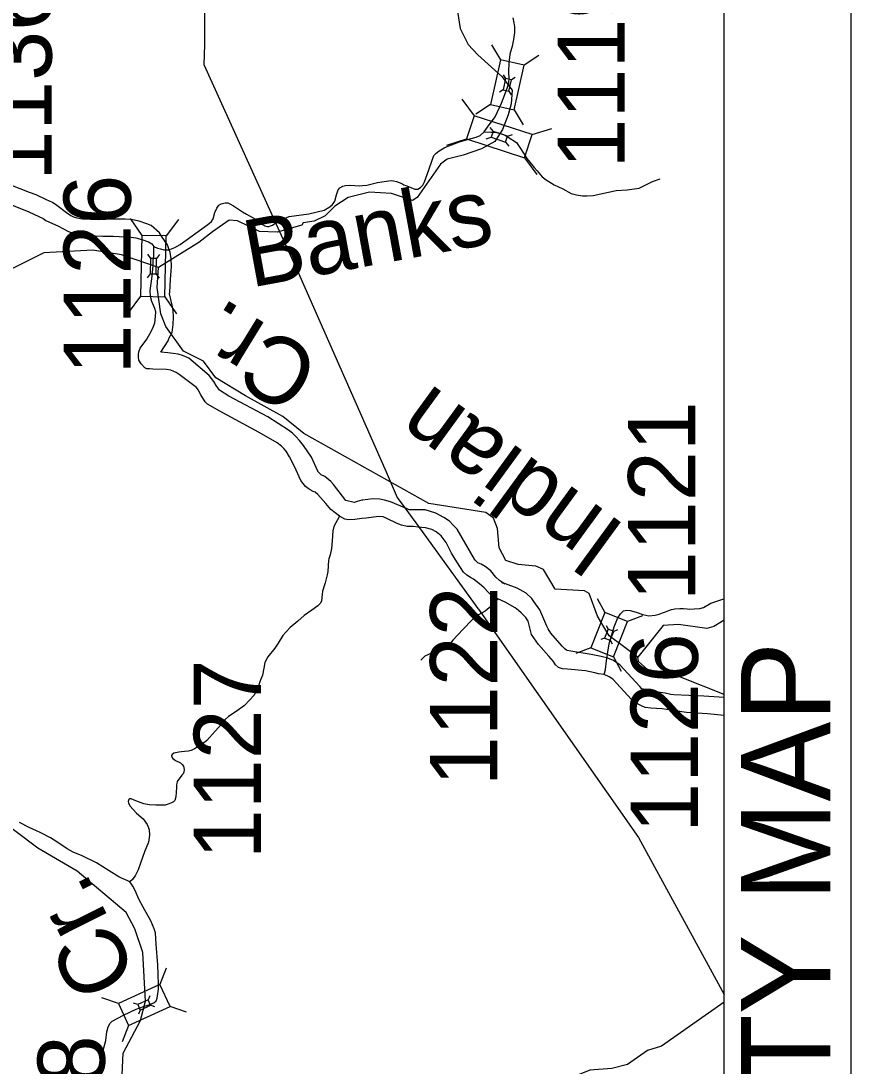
# Model space of a CAD drawing. Extents: x 264770 to 739672, y 157173 to 249791.
# Drawn here: x 727710 to 728336, y 158631 to 159419 of the extents above; entities that cross this region are included whole.
import ezdxf

# ---------------------------------------------------------------- set-up
doc = ezdxf.new("R2010")
doc.units = 0
for name, color, linetype in [('Old_Level_27', 7, 'Continuous'), ('Old_Level_5', 7, 'Continuous'), ('Prop Cable Guiderail Anchor Unit CELL', 7, 'Continuous'), ('Prop Cable Guiderail Single Face', 7, 'Continuous'), ('Prop Conc 2ft 6in Curb and Gutter', 7, 'Continuous'), ('Prop GRAU 350 Approach CELL', 7, 'Continuous'), ('Prop Guardrail Anchor Unit CELL', 7, 'Continuous'), ('Prop Lane Arrow Shared Lt and Thru CELL', 7, 'Continuous'), ('Prop ROW Station Offsets', 7, 'Continuous')]:
    doc.layers.add(name, color=color, linetype=linetype)

msp = doc.modelspace()

# ---------------------------------------------------------------- linework, layer by layer
at = {"layer": 'Old_Level_5'}
for points in [[(728193.27, 159467.91), (728173.62, 159472.65), (728164.12, 159479.96), (728126.72, 159480.62), (728119.2, 159483.78), (728071.56, 159489.46), (728066.92, 159486.7), (728052.97, 159455.09), (728043.68, 159437.89), (728039.77, 159426.35), (728041.58, 159413.46), (728047.77, 159401.58), (728054.96, 159393.65)], [(728054.96, 159393.65), (728073.01, 159377.28), (728080.84, 159367.08), (728080.21, 159356.86), (728077.92, 159348.46), (728073.58, 159337.51), (728067.85, 159328.35), (728057.78, 159322.88), (728044.05, 159318.19), (728031.82, 159315.1), (728026.92, 159311.2), (728009.2, 159286.14), (728005.71, 159283.93), (727989.98, 159289.13), (727973.24, 159290.3), (727957.32, 159286.18), (727947.08, 159279.54), (727939.82, 159272.21), (727931.48, 159268.42), (727923.41, 159266.94), (727922.23, 159265.23), (727903.76, 159260.04), (727890.46, 159260.5), (727873.86, 159268.66), (727867.57, 159269.11), (727854.98, 159260.35), (727844.61, 159252.16), (727839.26, 159248.86), (727814.14, 159233.36)], [(727814.14, 159233.36), (727786.19, 159242.83), (727764.61, 159246.42), (727727.83, 159244.55), (727698.6, 159229.8), (727682.21, 159225.12), (727664.77, 159225.14), (727659.53, 159227.66), (727647.4, 159229.24), (727639.07, 159226.03), (727629.13, 159211.21), (727614.24, 159201.22), (727611.1, 159193.75), (727620.47, 159180.01), (727617.34, 159172.53), (727597.65, 159174.96), (727591.65, 159173.41)], [(728175.64, 158939.69), (728154.15, 158955.6), (728145.26, 158970.5), (728138.95, 158987.63), (728135.54, 158989.51), (728113.3, 158990.85), (728104.41, 159005.75), (728098.72, 159008.28), (728085.42, 159009.32), (728076.07, 159012.56), (728071.22, 159022.07), (728069.9, 159036.68), (728066.84, 159044.38), (728060.95, 159048.67), (728018.16, 159055.41), (727923.7, 159108.25), (727907.88, 159121.05), (727879.73, 159136.6), (727857.5, 159150.22), (727848.11, 159162.79), (727833.11, 159170.31), (727819.7, 159188.86), (727815.98, 159198.32), (727813.17, 159218.25), (727814.14, 159233.36)], [(728240.88, 158967.57), (728233.04, 158962.78), (728227.73, 158961.22), (728206.43, 158964.29), (728194.71, 158963.53), (728175.64, 158939.69)], [(728240.88, 158911.43), (728207.94, 158924.56), (728185.29, 158928.28), (728176.26, 158936.18), (728175.64, 158939.69)], [(727786.89, 158624.71), (727787.45, 158641.02), (727800.56, 158665.66), (727804.53, 158680.1), (727802.28, 158716.94), (727796.43, 158734.63), (727789.79, 158747.12), (727752.99, 158778.14), (727723.25, 158795.51), (727675.98, 158830.99), (727666.23, 158848.82), (727659.48, 158855.48), (727637.57, 158862.06), (727581.54, 158861.66)], [(728240.88, 158679.51), (728193.45, 158646.22), (728183.06, 158643.08), (728167.92, 158632.53), (728156.15, 158629.43), (728139.37, 158628.26), (728131.5, 158625.02), (728124.9, 158616.5), (728114.35, 158582.47), (728098.42, 158543.34), (728095.35, 158538.78)]]:
    msp.add_lwpolyline(points, dxfattribs=at)
at = {"layer": 'Prop Conc 2ft 6in Curb and Gutter'}
for p, q in [((728065.25, 159401.22), (728072.03, 159389.93)), ((728100.91, 159393.21), (728089.95, 159385.91)), ((728074.22, 159378.65), (728075.92, 159375.83)), ((728083.14, 159376.65), (728080.4, 159374.82)), ((728074.03, 159367.43), (728071.29, 159365.61)), ((728078.51, 159366.42), (728080.21, 159363.6)), ((728042.95, 159360.36), (728052.22, 159347.78)), ((728064.49, 159356.35), (728053.52, 159349.04)), ((728082.4, 159352.32), (728089.18, 159341.03)), ((728064.14, 159339.05), (728066.46, 159335.91)), ((728061.31, 159330.37), (728065.04, 159331.55)), ((728077.37, 159332.36), (728081.09, 159333.54)), ((728095.87, 159333.58), (728110.76, 159338.3)), ((728031.65, 159325.61), (728046.54, 159330.32)), ((728075.95, 159328), (728078.27, 159324.85)), ((728090.19, 159316.12), (728099.46, 159303.54)), ((727792.77, 159270.43), (727801.6, 159257.54)), ((727829.31, 159269.67), (727819.96, 159257.16)), ((727805.92, 159243.41), (727808.13, 159240.19)), ((727815.05, 159243.22), (727812.71, 159240.09)), ((727807.89, 159228.72), (727805.55, 159225.59)), ((727812.47, 159228.62), (727814.68, 159225.4)), ((727800.64, 159211.65), (727791.29, 159199.14)), ((727819, 159211.27), (727827.83, 159198.38)), ((728145.1, 158983.92), (728150.69, 158973.22)), ((728179.15, 158970.66), (728167.8, 158966.56)), ((728151.81, 158963.38), (728153.2, 158960.7)), ((728150.6, 158954.02), (728147.76, 158952.99)), ((728160.32, 158960.06), (728157.48, 158959.04)), ((728140.28, 158946.49), (728128.93, 158942.39)), ((728154.88, 158952.35), (728156.28, 158949.68)), ((728157.39, 158939.83), (728162.99, 158929.13)), ((727820.08, 158705.13), (727815.22, 158692.89)), ((727783.94, 158678.51), (727771.48, 158682.8)), ((727798.54, 158677.65), (727795.43, 158678.72)), ((727807.58, 158684.3), (727806.36, 158681.24)), ((727811.39, 158676), (727808.28, 158677.07)), ((727800.46, 158673.47), (727799.24, 158670.41)), ((727835.34, 158671.92), (727822.88, 158676.2)), ((727791.6, 158661.83), (727786.74, 158649.59))]:
    msp.add_line(p, q, dxfattribs=at)
for points in [[(728082.4, 159352.32), (728089.95, 159385.91), (728072.03, 159389.93), (728064.49, 159356.35)], [(728095.87, 159333.58), (728052.22, 159347.78), (728046.54, 159330.32), (728090.19, 159316.12)], [(727819, 159211.27), (727819.96, 159257.16), (727801.6, 159257.54), (727800.64, 159211.65)], [(728157.39, 158939.83), (728167.8, 158966.56), (728150.69, 158973.22), (728140.28, 158946.49)], [(727791.6, 158661.83), (727822.88, 158676.2), (727815.22, 158692.89), (727783.94, 158678.51)]]:
    msp.add_lwpolyline(points, close=True, dxfattribs=at)
for points in [[(728078.51, 159366.42), (728080.4, 159374.82), (728075.92, 159375.83), (728074.03, 159367.43), (728078.51, 159366.42)], [(728077.37, 159332.36), (728066.46, 159335.91), (728065.04, 159331.55), (728075.95, 159328), (728077.37, 159332.36)], [(727812.47, 159228.62), (727812.71, 159240.09), (727808.13, 159240.19), (727807.89, 159228.72), (727812.47, 159228.62)], [(728154.88, 158952.35), (728157.48, 158959.04), (728153.2, 158960.7), (728150.6, 158954.02), (728154.88, 158952.35)], [(727800.46, 158673.47), (727808.28, 158677.07), (727806.36, 158681.24), (727798.54, 158677.65), (727800.46, 158673.47)]]:
    msp.add_lwpolyline(points, dxfattribs=at)
at = {"layer": 'Prop GRAU 350 Approach CELL'}
for p, q in [((728240.88, 157172.59), (728240.88, 160226.7)), ((728336.48, 157210.09), (728336.48, 160189.2))]:
    msp.add_line(p, q, dxfattribs=at)
at = {"layer": 'Prop Guardrail Anchor Unit CELL'}
for p, q in [((727848.8, 159459.04), (727848.9, 159401.21)), ((727848.9, 159401.21), (727848.43, 159386.41)), ((727848.43, 159386.41), (727903.06, 159266.08)), ((727903.06, 159266.08), (727919.86, 159229.08)), ((727919.86, 159229.08), (727985.81, 159079.32)), ((727985.81, 159079.32), (727994.28, 159060.07)), ((727994.28, 159060.07), (728000.07, 159052.09)), ((728000.07, 159052.09), (728011.03, 159036.98)), ((728055.39, 158975.81), (728176.24, 158803.57)), ((728176.24, 158803.57), (728240.88, 158685.14))]:
    msp.add_line(p, q, dxfattribs=at)
msp.add_lwpolyline([(728011.03, 159036.98), (728055.06, 158976.28), (728055.39, 158975.81)], dxfattribs=at)
at = {"layer": 'Prop Lane Arrow Shared Lt and Thru CELL'}
for points in [[(728078.44, 159372.68), (728078.6, 159376.17), (728078.47, 159380.39), (728078.67, 159388.28), (728079.59, 159395.38), (728081.14, 159400.22), (728082.16, 159405.24), (728082.82, 159410.63), (728082.95, 159412.84), (728082.82, 159414.74), (728082.35, 159417.9), (728081.7, 159421.58)], [(728059.7, 159335.79), (728062.4, 159339.27), (728068.05, 159347.04), (728072.85, 159357.29), (728075.48, 159363.74), (728077.32, 159369.46), (728078.44, 159372.68)], [(727810.71, 159249.28), (727813.41, 159248.03), (727815.81, 159247.34), (727818.28, 159246.58), (727820.57, 159246.58), (727822.26, 159246.79), (727822.78, 159246.85), (727826.58, 159248.41), (727830.66, 159250.62), (727851.31, 159265.74), (727854.27, 159268.17), (727855.39, 159270.14), (727856.77, 159274.81), (727858.15, 159278.16), (727859.73, 159280.33), (727861.37, 159281.39), (727864.52, 159282.25), (727866.49, 159282.05), (727868.01, 159281.46), (727870.83, 159279.94), (727877.55, 159275.34), (727880.64, 159273.5), (727882.81, 159272.38), (727885.18, 159271.07), (727887.34, 159269.72), (727889.43, 159268.67), (727890.96, 159267.35), (727892.68, 159265.73), (727894.31, 159264.9), (727896.32, 159264.26), (727897.47, 159264.3), (727898.59, 159264.69), (727900.23, 159265.41), (727903.32, 159267.45), (727904.84, 159268.37), (727907.34, 159269.69), (727912.81, 159271.73), (727927.68, 159273.83), (727939.13, 159276.51), (727943.34, 159279.07), (727945.38, 159280.91), (727947.09, 159283.48), (727948.47, 159288.08), (727949.79, 159291.96), (727950.89, 159293.41), (727953.26, 159294.59), (727955.3, 159295.12), (727958.53, 159295.45), (727962.21, 159295.18), (727965.7, 159295.05), (727968.07, 159295.12), (727971.29, 159295.38), (727979.47, 159297.42), (727984.41, 159298.34), (727987.83, 159298.73), (727989.87, 159298.86), (727991.45, 159298.67), (727993.62, 159298.21), (727997.61, 159296.59), (727999.25, 159295.69), (728001.53, 159294.91), (728007.56, 159292.49), (728009.66, 159292.55), (728011.7, 159293.67), (728013.48, 159295.51), (728014.86, 159297.88), (728016.9, 159303.6), (728019.97, 159312.81), (728021.91, 159317.78), (728023.52, 159319.64), (728025.82, 159321.35), (728029.5, 159323.65), (728033.24, 159325.2), (728041.27, 159328.09), (728048.97, 159330.39), (728053.85, 159331.71), (728056.68, 159333.02), (728059.7, 159335.79)], [(728059.7, 159335.79), (728064.9, 159335.52), (728068.72, 159335.46), (728071.28, 159334.6), (728074.27, 159333.62)], [(728074.27, 159333.62), (728077.76, 159331.58), (728084.21, 159327.5), (728086.64, 159323.95), (728089.86, 159318.76), (728091.9, 159315.53), (728097.43, 159308.69), (728099.86, 159306.2), (728103.62, 159301.65), (728106.51, 159299.42), (728112.63, 159295.8), (728119.14, 159292.71), (728125.39, 159289.09), (728129.41, 159288.24), (728133.81, 159287.38), (728137.3, 159287.32), (728142.1, 159287.71), (728159.34, 159291.53), (728167.57, 159291.92), (728176.57, 159293.3), (728186.63, 159298.23), (728192.42, 159300.27)], [(727692.76, 159284.57), (727712.08, 159277.06), (727716.55, 159275.46), (727723.92, 159271.89), (727727.29, 159270.36), (727729.37, 159268.89), (727738.81, 159264.5), (727745.79, 159260.69), (727750.13, 159259.11), (727753.55, 159258.32), (727758.55, 159257.79), (727766.71, 159257.27), (727772.16, 159256.97), (727780.18, 159256.91), (727784.58, 159256.71), (727791.95, 159256.38), (727797.18, 159255.66), (727801.66, 159254.54), (727806.72, 159252.7), (727809.16, 159251.25), (727810.71, 159249.28)], [(727810.26, 159234.68), (727810.25, 159238.95), (727810.58, 159241.72), (727810.65, 159243.82), (727810.65, 159246.19), (727810.71, 159249.28)], [(727950.66, 159045.77), (727944.14, 159051.03), (727940.41, 159055.44), (727934.36, 159062.32), (727932.33, 159063.86), (727930.92, 159064.55), (727928.55, 159065.74), (727927.05, 159066.75), (727925.09, 159068.27), (727921.6, 159072.88), (727916.86, 159083.21), (727912.98, 159090.64), (727910.49, 159094.84), (727908.78, 159097.01), (727906.94, 159098.72), (727903.65, 159101.23), (727890.18, 159108.99), (727860, 159125.24), (727853.31, 159128.98), (727851.14, 159130.44), (727849.43, 159132.2), (727846.12, 159137.47), (727844.15, 159141.15), (727842.77, 159142.91), (727829.87, 159152.77), (727827.64, 159154.1), (727825.86, 159155.01), (727823.42, 159156.06), (727820.26, 159156.52), (727809.93, 159156.65), (727807.43, 159156.85), (727805.46, 159157.05), (727804.01, 159157.64), (727801.12, 159160.67), (727799.47, 159163.5), (727799.14, 159166.06), (727799.17, 159167.8), (727799.28, 159169.75), (727800.46, 159172.51), (727805.53, 159179.41), (727808.95, 159185.59), (727810.13, 159188.49), (727811.49, 159191.66), (727811.91, 159196.34), (727812.11, 159199.83), (727811.45, 159202.53), (727809.28, 159207.65), (727808.16, 159211.47), (727807.83, 159216.07), (727809.15, 159224.82), (727810.26, 159234.68)], [(727950.66, 159045.77), (727946.31, 159038.08), (727945.66, 159034.86), (727945.26, 159027.18), (727944.6, 159021.39), (727943.68, 159016.72), (727942.56, 159013.83), (727942.38, 159012.8), (727942.1, 159008.38), (727941.93, 159004.18), (727941.44, 159001.76), (727939.8, 158995.58), (727937.96, 158989.27), (727937.63, 158986.77), (727937.23, 158982.17), (727936.38, 158980.19), (727934.34, 158978.16), (727929.8, 158975), (727924.09, 158970.9), (727919.39, 158966.73), (727913.53, 158961.93), (727910.24, 158958.44), (727907.94, 158955.83), (727904.46, 158950.18), (727901.95, 158946.36), (727896.76, 158939.72), (727894.28, 158935.5), (727893.69, 158931.29), (727892.62, 158926.05), (727890.86, 158921.69), (727890.07, 158919.46), (727889.55, 158918.07), (727887.31, 158912.81), (727886.19, 158910.64), (727882.9, 158907.09), (727879.05, 158903.14), (727872.79, 158898.64), (727866.93, 158894.72), (727864.31, 158892.27), (727862.9, 158890.55), (727861.67, 158889.06), (727856.88, 158883.8), (727850.78, 158876.81), (727849.1, 158875.42), (727841.47, 158870.38), (727838.96, 158869.19), (727836.75, 158868.69), (727833.72, 158868.54), (727831.6, 158868.26), (727829.48, 158867.98), (727825.7, 158867.16), (727824.39, 158866.18), (727824.1, 158865.54), (727824.17, 158864.14), (727825.07, 158863.09), (727827.06, 158861.76), (727830.88, 158859.87), (727832.14, 158858.7), (727832.94, 158857.28), (727833.62, 158854.77), (727833.4, 158852.82), (727832.83, 158851.68), (727831.7, 158850.51), (727828.3, 158845.8), (727828.06, 158844.29), (727827.89, 158843.24), (727827.66, 158841.27), (727827.25, 158834.28), (727826.46, 158831.61), (727825.52, 158830.43), (727824.04, 158829.8), (727821.49, 158828.71), (727819.32, 158828.05), (727812.28, 158828.05), (727807.08, 158828.11), (727803.26, 158828.97), (727797.21, 158831.14), (727793.51, 158832.72), (727792.59, 158832.78), (727791.87, 158832.13), (727791.6, 158831.6), (727791.41, 158830.81), (727791.54, 158829.76), (727792.66, 158827.39), (727797.59, 158822), (727802.59, 158817.78), (727805.62, 158813.45), (727807.07, 158809.51), (727807.46, 158805.36), (727806.61, 158799.96), (727803.64, 158792.73), (727800.68, 158784.2), (727798.84, 158779.13), (727796.87, 158775.32), (727794.5, 158772.03), (727792.53, 158770.12)], [(728070.18, 158983.43), (728066.08, 158985.56), (728063.7, 158987.53), (728062.76, 158988.52), (728059.72, 158991.8), (728056.27, 158994.92), (728051.67, 158998.37), (728049.37, 158999.6), (728046.66, 159001.4), (728044.12, 159003.78), (728041.82, 159007.23), (728039.17, 159011.48), (728035.15, 159018.05), (728031.04, 159025.93), (728027.35, 159031.02), (728023.57, 159033.97), (728020.29, 159035.94), (728015.64, 159037.17), (728010.13, 159037.66), (728006.19, 159037.99), (728001.84, 159037.99), (727997.57, 159039.06), (727994.06, 159040.29), (727986.5, 159044.23), (727983.54, 159045.46), (727980.18, 159045.71), (727970.74, 159044.47), (727967.45, 159044.07), (727962.19, 159043.41), (727957.76, 159043.24), (727954.72, 159043.74), (727950.66, 159045.77)], [(728070.18, 158983.43), (728066.24, 158979.08), (728060.58, 158974.17), (728055.48, 158971.46), (728053.1, 158969.98), (728050.15, 158967.28), (728044.23, 158961.04), (728039.63, 158956.28), (728036.12, 158952.31), (728033.66, 158949.19), (728031.77, 158947.05), (728028.07, 158945.16), (728023.37, 158943.67), (728020.04, 158942.5), (728015.13, 158940.25), (728013.45, 158938.93), (728012.1, 158937.35)], [(728150.22, 158926.44), (728146.03, 158926.94), (728143.24, 158927.67), (728136.16, 158929.32), (728122.57, 158930.52), (728118.75, 158930.79), (728115.89, 158931.86), (728113.68, 158933.75), (728112.03, 158936.19), (728108.67, 158940.3), (728100.7, 158949.24), (728095.46, 158956.63), (728093.08, 158966.64), (728091.11, 158969.43), (728087.66, 158972.96), (728085.69, 158974.77), (728083.26, 158976.69), (728075.67, 158981.01), (728070.18, 158983.43)], [(728156.13, 158956.32), (728157.78, 158962.47), (728160.4, 158968.63), (728162.62, 158972.24), (728164.89, 158974.41), (728167.27, 158974.98), (728169.78, 158974.74), (728174.39, 158973.47), (728179.31, 158971.62), (728183.91, 158970.8), (728188.67, 158971.13), (728191.87, 158972.11), (728194.17, 158972.93), (728196.46, 158973.75), (728199, 158974.74), (728201.14, 158975.39), (728203.65, 158975.89), (728207.3, 158976.3), (728210.09, 158976.3), (728212.96, 158976.05), (728214.84, 158975.79), (728218.06, 158975.93), (728222.29, 158976.21), (728225.08, 158977.03), (728230.73, 158980.32), (728240.51, 158983.52), (728240.88, 158983.73)], [(728150.22, 158926.44), (728151.22, 158930.38), (728152.03, 158936.78), (728153.34, 158945.07), (728154.08, 158949.34), (728154.49, 158951.56), (728156.13, 158956.32)], [(728240.88, 158895.7), (728228.11, 158896.86), (728212.42, 158897.92), (728203.88, 158899.15), (728194.04, 158900.55), (728185.42, 158901.04), (728181.07, 158901.7), (728178.36, 158902.77), (728175.32, 158904.33), (728170.78, 158907.53), (728156.74, 158922.87), (728154.11, 158924.76), (728150.22, 158926.44)], [(727792.53, 158770.12), (727791.19, 158770.81), (727785.79, 158773.27), (727784.22, 158773.98), (727777.08, 158778.57), (727767.58, 158784.59), (727756.65, 158789.74), (727749.83, 158792.43), (727745.4, 158794.96), (727738.27, 158799.87), (727732.88, 158803.35), (727725.59, 158807.07), (727722.16, 158808.67), (727716.72, 158811.19), (727709.43, 158814.99)], [(727812.53, 158723.09), (727811.87, 158731.84), (727811.01, 158734.66), (727808.38, 158740.65), (727802.66, 158751.1), (727799.45, 158757.19), (727796.64, 158763.56), (727794.87, 158766.83), (727793.8, 158768.39), (727792.53, 158770.12)], [(727802.86, 158676.19), (727806.21, 158677.3), (727808.65, 158678.09), (727810.69, 158679.01), (727812.4, 158680.39), (727813.32, 158682.56), (727814.17, 158689.27), (727814.3, 158693.28), (727814.04, 158700.37), (727813.78, 158707.67), (727812.53, 158723.09)], [(727770.86, 158631), (727771, 158634.35), (727771.33, 158636.85), (727772.25, 158642.27), (727774.42, 158650.49), (727775.34, 158657), (727776.26, 158660.88), (727777.71, 158663.51), (727779.29, 158665.22), (727787.85, 158669.68), (727797.39, 158674.08), (727802.86, 158676.19)]]:
    msp.add_lwpolyline(points, dxfattribs=at)
at = {"layer": 'Prop ROW Station Offsets'}
msp.add_line((728075.95, 158994.86), (728074.29, 158995.49), dxfattribs=at)
for points in [[(727822.26, 159246.79), (727820.96, 159250.4), (727816.59, 159256.9), (727814.96, 159259.55), (727808.7, 159264.96), (727805.44, 159266.36), (727799.54, 159268.35), (727793.66, 159269.55), (727788.97, 159269.85), (727786.05, 159269.78), (727772.22, 159269.78), (727769.08, 159269.34), (727756.98, 159269.82), (727755.19, 159270.07), (727752.9, 159270.58), (727750.41, 159271.36), (727748.75, 159271.98), (727748.16, 159272.3), (727744.75, 159274.59), (727737.45, 159280.04), (727734.16, 159282.35), (727729.78, 159284.36), (727721.89, 159288.17), (727716.9, 159289.97), (727697.05, 159297.67)], [(727967.54, 159057.87), (727964.08, 159056.97), (727961.74, 159056.27), (727955.55, 159057.77), (727946.09, 159069.8), (727944.1, 159072.12), (727939.67, 159075.86), (727936.82, 159077.01), (727934.44, 159079.63), (727934.24, 159079.93), (727929.59, 159090.25), (727923.55, 159099.22), (727920.52, 159103.02), (727917.89, 159106.04), (727915.16, 159108.52), (727912.17, 159110.82), (727896.77, 159120.66), (727867.14, 159136.36), (727860.95, 159140.44), (727860.12, 159141), (727857.8, 159144.49), (727855.83, 159147.48), (727852.31, 159151.82), (727837.17, 159164.96), (727832.39, 159167.05), (727828.92, 159168.09), (727825.29, 159168.58), (727821.36, 159169.12), (727815.94, 159169.57), (727821.51, 159178.13), (727822.35, 159180.38), (727824.39, 159184.39), (727825.22, 159190.42), (727825.45, 159196.04), (727825.17, 159200.96), (727824.48, 159205.09), (727822.51, 159213.41), (727822.66, 159214.84), (727823.33, 159224.41), (727824.02, 159234.09), (727823.75, 159239.97), (727822.92, 159244.96), (727822.26, 159246.79)], [(728000.07, 159052.09), (727989.24, 159056.75), (727984.66, 159057.86), (727981.02, 159058.6), (727975.89, 159058.86), (727968.28, 159058.06), (727967.54, 159057.87)], [(728074.29, 158995.49), (728071.24, 158997.32), (728068.58, 158999.84), (728064.85, 159004.77), (728060.58, 159007.92), (728057.55, 159009.78), (728055.13, 159010.79), (728054.88, 159011), (728053.79, 159011.93), (728053.25, 159012.53), (728052.57, 159013.5), (728039.37, 159036.12), (728036.48, 159039.06), (728033.67, 159042.05), (728029.41, 159044.96), (728023.34, 159048.15), (728015.4, 159050.64), (728010.55, 159050.77), (728006.48, 159050.77), (728003.33, 159050.6), (728001.84, 159051.33), (728000.07, 159052.09)], [(728074.29, 158995.49), (728073.18, 158995.92), (728075.31, 158994.89), (728074.29, 158995.49)], [(728150.1, 158939.58), (728148.06, 158940.01), (728140.42, 158941.56), (728125.24, 158944.03), (728122.38, 158944.7), (728121.88, 158944.9), (728120.96, 158945.51), (728119.75, 158946.51), (728118.59, 158947.89), (728110.06, 158957.66), (728108.06, 158960.84), (728106.94, 158962.86), (728101.72, 158975.36), (728097.25, 158981.57), (728095.69, 158983.76), (728091.49, 158987.92), (728084.68, 158991.49), (728075.95, 158994.86)], [(728240.88, 158909.07), (728225.34, 158910.07), (728202.77, 158911.18), (728200.6, 158911.43), (728196.15, 158912.53), (728190.72, 158913.27), (728179.91, 158915.43), (728178.64, 158915.68), (728177.11, 158917.35), (728162.21, 158933.77), (728156.85, 158937.41), (728152.34, 158939.1), (728150.1, 158939.58)]]:
    msp.add_lwpolyline(points, dxfattribs=at)

# ---------------------------------------------------------------- texts
at = {"layer": 'Old_Level_27'}
for s, rotation, p in [('Banks', 10.42581, (727883.74, 159218.14)), ('Cr.', 148.50502, (727939.08, 159164.09)), ('Indian', 143.91441, (728167.86, 159037.72)), ('Cr.', 116.63123, (727798.99, 158698.7))]:
    msp.add_text(s, height=50.625, rotation=rotation, dxfattribs=at).set_placement(p)
at = {"layer": 'Prop Cable Guiderail Anchor Unit CELL'}
msp.add_text('VICINITY MAP', height=67.5, rotation=90, dxfattribs=at).set_placement((728320.94, 158349.32))
at = {"layer": 'Prop Cable Guiderail Single Face'}
for s, p in [('1119', (728165.82, 159307.99)), ('1136', (727733.65, 159298.83)), ('1126', (727793.29, 159152.68)), ('1121', (728218.95, 158981.84)), ('1122', (728069.63, 158842.26)), ('1126', (728220.91, 158807.05)), ('1127', (727891.44, 158787.25)), ('1128', (727773.68, 158503.84))]:
    msp.add_text(s, height=50.625, rotation=90, dxfattribs=at).set_placement(p)

doc.saveas('drawing.dxf')
